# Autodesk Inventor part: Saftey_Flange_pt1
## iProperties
Shininess: 64.0
Length Units: 11269
Angle Units: 11279
Time Units: 11290
Mass Units: 11283
Length Display Precision: 3
Angle Display Precision: 2
Compacted: True
Part Number: Saftey_Flange_pt1
Document SubType Name: Modeling
Created: 2004-07
Designer: John Blackburn
Manufacturer: Standard
Standards Organization: Custom
Project: Mucap
Material: Stainless Steel, Austenitic
Description: Mucap, Be Window, Saftey Flange
Density: 0.0
Volumn: 0.0
Area: 0.0
PropertySet Name: Model Information
Control State: 0
Master: False
Checked Out: False
Author: John Blackburn
Title: Mucap, Saftey Flange
Subject: Mucap
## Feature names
1. Extrusion1
2. Chamfer1
3. Hole1
4. Circular Pattern1
5. Extrusion3
